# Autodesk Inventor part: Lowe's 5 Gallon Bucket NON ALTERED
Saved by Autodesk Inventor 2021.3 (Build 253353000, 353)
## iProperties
Created: 2022-12
Part Number: Lowe's 5 Gallon Bucket NON ALTERED
Material: Generic
Document SubType Name: Modeling
Designer: AdminForWorker
Density: 1 g/cm^3
Appearance: Default
Title: Lowe's 5 Gallon Bucket NON ALTERED
Author: AdminForWorker
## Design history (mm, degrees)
feature "Body1"
body "Solid1"
